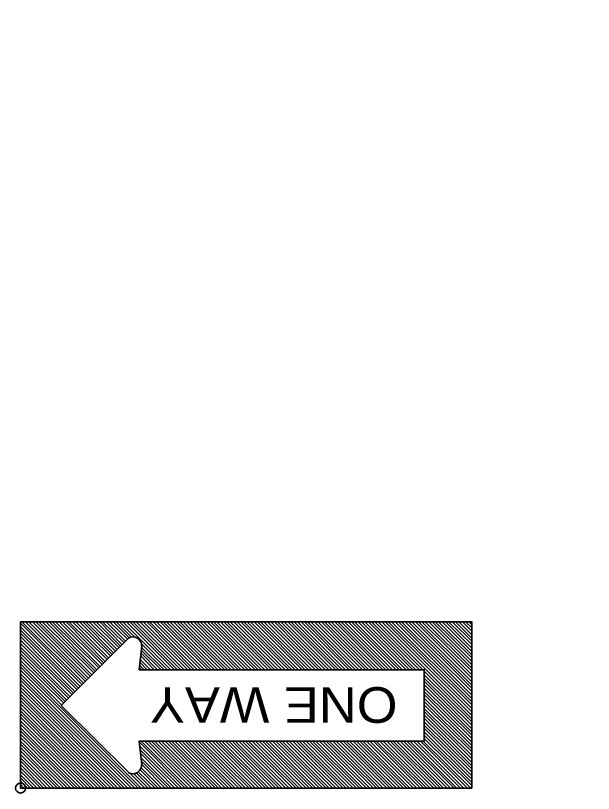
# Model space of a CAD drawing. Extents: x -133 to 547, y -328 to 112.
# Drawn here: x 275.99 to 299.34, y -0.08 to 31.36 of the extents above; entities that cross this region are included whole.
import ezdxf
from ezdxf.enums import TextEntityAlignment as Align

# ---------------------------------------------------------------- set-up
doc = ezdxf.new("R2010")
doc.units = 0
doc.header["$LTSCALE"] = 0.8
doc.header["$PDMODE"] = 32
doc.header["$PDSIZE"] = 0.4
doc.layers.add('1', color=7, linetype='Continuous', lineweight=35)

msp = doc.modelspace()

# ---------------------------------------------------------------- linework, layer by layer
at = {"layer": '1'}
for p, q in [((276.1893, 6.7957), (278.6692, 4.3157)), ((276.1893, 6.6557), (278.5892, 4.2557)), ((276.2493, 6.8557), (278.7292, 4.3757)), ((276.3893, 6.8557), (278.8092, 4.4557)), ((276.5292, 6.8557), (278.8692, 4.5157)), ((276.6692, 6.8557), (278.9292, 4.5957)), ((276.8092, 6.8557), (279.0093, 4.6557)), ((276.9292, 6.8557), (279.0693, 4.7157)), ((277.0693, 6.8557), (279.1492, 4.7957)), ((277.2092, 6.8557), (279.2092, 4.8557)), ((277.3492, 6.8557), (279.2692, 4.9157)), ((277.4692, 6.8557), (279.3492, 4.9957)), ((277.6092, 6.8557), (279.4092, 5.0557)), ((277.7493, 6.8557), (279.4892, 5.1357)), ((277.8893, 6.8557), (279.5492, 5.1957)), ((278.0292, 6.8557), (279.6092, 5.2557)), ((278.1492, 6.8557), (279.6893, 5.3357)), ((278.2892, 6.8557), (279.7493, 5.3957)), ((278.4292, 6.8557), (279.8293, 5.4757)), ((278.5693, 6.8557), (279.8893, 5.5357)), ((278.7092, 6.8557), (279.9493, 5.5957)), ((278.8293, 6.8557), (280.0292, 5.6757)), ((278.9692, 6.8557), (280.0892, 5.7357)), ((279.1092, 6.8557), (280.1692, 5.8157)), ((279.2493, 6.8557), (280.2292, 5.8757)), ((279.3893, 6.8557), (280.2892, 5.9357)), ((279.5093, 6.8557), (280.3692, 6.0157)), ((279.6492, 6.8557), (280.4292, 6.0757)), ((279.7892, 6.8557), (280.5093, 6.1557)), ((279.9292, 6.8557), (280.5693, 6.2157)), ((280.0492, 6.8557), (280.6692, 6.2357)), ((280.1893, 6.8557), (280.8092, 6.2357)), ((280.3293, 6.8557), (282.2692, 4.9157)), ((280.4692, 6.8557), (282.4092, 4.9157)), ((280.6092, 6.8557), (282.5292, 4.9157)), ((280.7292, 6.8557), (282.6692, 4.9157)), ((280.8692, 6.8557), (282.8092, 4.9157)), ((281.0093, 6.8557), (282.9493, 4.9157)), ((281.1492, 6.8557), (283.0892, 4.9157)), ((281.2892, 6.8557), (283.2092, 4.9157)), ((281.4092, 6.8557), (283.3492, 4.9157)), ((281.5492, 6.8557), (283.4892, 4.9157)), ((281.6893, 6.8557), (283.6293, 4.9157)), ((281.8293, 6.8557), (283.7692, 4.9157)), ((281.9493, 6.8557), (283.8893, 4.9157)), ((282.0892, 6.8557), (284.0292, 4.9157)), ((282.2292, 6.8557), (284.1692, 4.9157)), ((282.3692, 6.8557), (284.3092, 4.9157)), ((282.5093, 6.8557), (284.4493, 4.9157)), ((282.6293, 6.8557), (284.5693, 4.9157)), ((282.7692, 6.8557), (284.7092, 4.9157)), ((282.9092, 6.8557), (284.8492, 4.9157)), ((283.0492, 6.8557), (284.9892, 4.9157)), ((283.1893, 6.8557), (285.1092, 4.9157)), ((283.3092, 6.8557), (285.2493, 4.9157)), ((283.4493, 6.8557), (285.3893, 4.9157)), ((283.5892, 6.8557), (285.5292, 4.9157)), ((283.7292, 6.8557), (285.6692, 4.9157)), ((283.8692, 6.8557), (285.7892, 4.9157)), ((283.9892, 6.8557), (285.9292, 4.9157)), ((284.1293, 6.8557), (286.0693, 4.9157)), ((284.2692, 6.8557), (286.2092, 4.9157)), ((284.4092, 6.8557), (286.3492, 4.9157)), ((284.5292, 6.8557), (286.4692, 4.9157)), ((284.6692, 6.8557), (286.6092, 4.9157)), ((284.8092, 6.8557), (286.7493, 4.9157)), ((284.9493, 6.8557), (286.8893, 4.9157)), ((285.0892, 6.8557), (287.0292, 4.9157)), ((285.2092, 6.8557), (287.1492, 4.9157)), ((285.3492, 6.8557), (287.2892, 4.9157)), ((285.4892, 6.8557), (287.4292, 4.9157)), ((285.6293, 6.8557), (287.5693, 4.9157)), ((285.7692, 6.8557), (287.6893, 4.9157)), ((285.8893, 6.8557), (287.8293, 4.9157)), ((286.0292, 6.8557), (287.9692, 4.9157)), ((286.1692, 6.8557), (288.1092, 4.9157)), ((286.3092, 6.8557), (288.2493, 4.9157)), ((286.4493, 6.8557), (288.3692, 4.9157)), ((286.5693, 6.8557), (288.5093, 4.9157)), ((286.7092, 6.8557), (288.6492, 4.9157)), ((286.8492, 6.8557), (288.7892, 4.9157)), ((286.9892, 6.8557), (288.9292, 4.9157)), ((287.1092, 6.8557), (289.0492, 4.9157)), ((287.2493, 6.8557), (289.1893, 4.9157)), ((287.3893, 6.8557), (289.3293, 4.9157)), ((287.5292, 6.8557), (289.4692, 4.9157)), ((287.6692, 6.8557), (289.5892, 4.9157)), ((287.7892, 6.8557), (289.7292, 4.9157)), ((287.9292, 6.8557), (289.8692, 4.9157)), ((288.0693, 6.8557), (290.0093, 4.9157)), ((288.2092, 6.8557), (290.1492, 4.9157)), ((288.3492, 6.8557), (290.2692, 4.9157)), ((288.4692, 6.8557), (290.4092, 4.9157)), ((288.6092, 6.8557), (290.5492, 4.9157)), ((288.7493, 6.8557), (290.6893, 4.9157)), ((288.8893, 6.8557), (290.8293, 4.9157)), ((289.0093, 6.8557), (290.9493, 4.9157)), ((289.1492, 6.8557), (291.0892, 4.9157)), ((289.2892, 6.8557), (291.2292, 4.9157)), ((289.4292, 6.8557), (291.3692, 4.9157)), ((289.5693, 6.8557), (291.5093, 4.9157)), ((289.6893, 6.8557), (291.6293, 4.9157)), ((289.8293, 6.8557), (291.7692, 4.9157)), ((289.9692, 6.8557), (291.9092, 4.9157)), ((290.1092, 6.8557), (292.0492, 4.9157)), ((290.2493, 6.8557), (292.1692, 4.9157)), ((290.3692, 6.8557), (292.3092, 4.9157)), ((290.5093, 6.8557), (292.4493, 4.9157)), ((290.6492, 6.8557), (294.4292, 3.0757)), ((290.7892, 6.8557), (294.4292, 3.2157)), ((290.9292, 6.8557), (294.4292, 3.3557)), ((291.0492, 6.8557), (294.4292, 3.4957)), ((291.1893, 6.8557), (294.4292, 3.6157)), ((291.3293, 6.8557), (294.4292, 3.7557)), ((291.4692, 6.8557), (294.4292, 3.8957)), ((291.5892, 6.8557), (294.4292, 4.0357)), ((291.7292, 6.8557), (294.4292, 4.1757)), ((291.8692, 6.8557), (294.4292, 4.2957)), ((292.0093, 6.8557), (294.4292, 4.4357)), ((292.1492, 6.8557), (294.4292, 4.5757)), ((292.2692, 6.8557), (294.4292, 4.7157)), ((292.4092, 6.8557), (294.4292, 4.8557)), ((292.5492, 6.8557), (294.4292, 4.9757)), ((292.6893, 6.8557), (294.4292, 5.1157)), ((292.8293, 6.8557), (294.4292, 5.2557)), ((292.9493, 6.8557), (294.4292, 5.3957)), ((293.0892, 6.8557), (294.4292, 5.5157)), ((293.2292, 6.8557), (294.4292, 5.6557)), ((293.3692, 6.8557), (294.4292, 5.7957)), ((293.4892, 6.8557), (294.4292, 5.9357)), ((293.6293, 6.8557), (294.4292, 6.0757)), ((293.7692, 6.8557), (294.4292, 6.1957)), ((293.9092, 6.8557), (294.4292, 6.3357)), ((294.0492, 6.8557), (294.4292, 6.4757)), ((294.1692, 6.8557), (294.4292, 6.6157)), ((294.3092, 6.8557), (294.4292, 6.7557)), ((276.1893, 6.5157), (278.5292, 4.1757)), ((276.1893, 6.3957), (278.4692, 4.1157)), ((276.1893, 6.2557), (278.3893, 4.0357)), ((276.1893, 6.1157), (278.3293, 3.9757)), ((276.1893, 5.9757), (278.2692, 3.9157)), ((280.5492, 6.1957), (277.8293, 3.4757)), ((281.0693, 5.9757), (282.1293, 4.9157)), ((276.1893, 5.8357), (278.1893, 3.8357)), ((276.1893, 5.7157), (278.1293, 3.7757)), ((281.0693, 5.8357), (281.9892, 4.9157)), ((281.0693, 5.7157), (281.8692, 4.9157)), ((276.1893, 5.5757), (278.0492, 3.6957)), ((276.1893, 5.4357), (277.9892, 3.6357)), ((281.0492, 5.5957), (281.7292, 4.9157)), ((281.0492, 5.4757), (281.5892, 4.9157)), ((276.1893, 5.2957), (277.9292, 3.5757)), ((276.1893, 5.1557), (277.8492, 3.4957)), ((276.1893, 5.0357), (281.0693, 0.1357)), ((281.0093, 5.0957), (281.1893, 4.9157)), ((281.0292, 5.3357), (281.4493, 4.9157)), ((281.0292, 5.2157), (281.3092, 4.9157)), ((276.1893, 4.8957), (280.9493, 0.1357)), ((276.1893, 4.7557), (280.8092, 0.1357)), ((281.0093, 4.9757), (281.0492, 4.9157)), ((292.5093, 4.8557), (294.4292, 2.9357)), ((292.5093, 4.7157), (294.4292, 2.8157)), ((276.1893, 4.6157), (280.6692, 0.1357)), ((276.1893, 4.4957), (280.5292, 0.1357)), ((292.5093, 4.5757), (294.4292, 2.6757)), ((292.5093, 4.4557), (294.4292, 2.5357)), ((276.1893, 4.3557), (280.3893, 0.1357)), ((276.1893, 4.2157), (280.2692, 0.1357)), ((292.5093, 4.3157), (294.4292, 2.3957)), ((292.5093, 4.1757), (294.4292, 2.2757)), ((276.1893, 4.0757), (280.1293, 0.1357)), ((276.1893, 3.9357), (279.9892, 0.1357)), ((276.1893, 3.8157), (279.8492, 0.1357)), ((292.5093, 4.0357), (294.4292, 2.1357)), ((292.5093, 3.9157), (294.4292, 1.9957)), ((292.5093, 3.7757), (294.4292, 1.8557)), ((276.1893, 3.6757), (279.7092, 0.1357)), ((276.1893, 3.5357), (279.5892, 0.1357)), ((277.8293, 3.4757), (280.5492, 0.7757)), ((292.5093, 3.6357), (294.4292, 1.7157)), ((292.5093, 3.4957), (294.4292, 1.5957)), ((276.1893, 3.3957), (279.4493, 0.1357)), ((276.1893, 3.2557), (279.3092, 0.1357)), ((292.5093, 3.3557), (294.4292, 1.4557)), ((292.5093, 3.2357), (294.4292, 1.3157)), ((276.1893, 3.1357), (279.1692, 0.1357)), ((276.1893, 2.9957), (279.0492, 0.1357)), ((276.1893, 2.8557), (278.9092, 0.1357)), ((292.5093, 3.0957), (294.4292, 1.1757)), ((292.5093, 2.9557), (294.4292, 1.0357)), ((276.1893, 2.7157), (278.7692, 0.1357)), ((276.1893, 2.5757), (278.6293, 0.1357)), ((292.5093, 2.8157), (294.4292, 0.9157)), ((292.5093, 2.6757), (294.4292, 0.7757)), ((292.5093, 2.5557), (294.4292, 0.6357)), ((276.1893, 2.4557), (278.4892, 0.1357)), ((276.1893, 2.3157), (278.3692, 0.1357)), ((292.5093, 2.4157), (294.4292, 0.4957)), ((292.5093, 2.2757), (294.4292, 0.3557)), ((276.1893, 2.1757), (278.2292, 0.1357)), ((276.1893, 2.0357), (278.0892, 0.1357)), ((276.1893, 1.9157), (277.9493, 0.1357)), ((281.0093, 1.9757), (282.8492, 0.1357)), ((281.0693, 2.0357), (282.9692, 0.1357)), ((281.2092, 2.0357), (283.1092, 0.1357)), ((281.3492, 2.0357), (283.2493, 0.1357)), ((281.4892, 2.0357), (283.3893, 0.1357)), ((281.6092, 2.0357), (283.5292, 0.1357)), ((281.7493, 2.0357), (283.6492, 0.1357)), ((281.8893, 2.0357), (283.7892, 0.1357)), ((282.0292, 2.0357), (283.9292, 0.1357)), ((282.1692, 2.0357), (284.0693, 0.1357)), ((282.2892, 2.0357), (284.1893, 0.1357)), ((282.4292, 2.0357), (284.3293, 0.1357)), ((282.5693, 2.0357), (284.4692, 0.1357)), ((282.7092, 2.0357), (284.6092, 0.1357)), ((282.8492, 2.0357), (284.7493, 0.1357)), ((282.9692, 2.0357), (284.8692, 0.1357)), ((283.1092, 2.0357), (285.0093, 0.1357)), ((283.2493, 2.0357), (285.1492, 0.1357)), ((283.3893, 2.0357), (285.2892, 0.1357)), ((283.5093, 2.0357), (285.4292, 0.1357)), ((283.6492, 2.0357), (285.5492, 0.1357)), ((283.7892, 2.0357), (285.6893, 0.1357)), ((283.9292, 2.0357), (285.8293, 0.1357)), ((284.0693, 2.0357), (285.9692, 0.1357)), ((284.1893, 2.0357), (286.1092, 0.1357)), ((284.3293, 2.0357), (286.2292, 0.1357)), ((284.4692, 2.0357), (286.3692, 0.1357)), ((284.6092, 2.0357), (286.5093, 0.1357)), ((284.7493, 2.0357), (286.6492, 0.1357)), ((284.8692, 2.0357), (286.7692, 0.1357)), ((285.0093, 2.0357), (286.9092, 0.1357)), ((285.1492, 2.0357), (287.0492, 0.1357)), ((285.2892, 2.0357), (287.1893, 0.1357)), ((285.4092, 2.0357), (287.3293, 0.1357)), ((285.5492, 2.0357), (287.4493, 0.1357)), ((285.6893, 2.0357), (287.5892, 0.1357)), ((285.8293, 2.0357), (287.7292, 0.1357)), ((285.9692, 2.0357), (287.8692, 0.1357)), ((286.0892, 2.0357), (288.0093, 0.1357)), ((286.2292, 2.0357), (288.1293, 0.1357)), ((286.3692, 2.0357), (288.2692, 0.1357)), ((286.5093, 2.0357), (288.4092, 0.1357)), ((286.6492, 2.0357), (288.5492, 0.1357)), ((286.7692, 2.0357), (288.6692, 0.1357)), ((286.9092, 2.0357), (288.8092, 0.1357)), ((287.0492, 2.0357), (288.9493, 0.1357)), ((287.1893, 2.0357), (289.0892, 0.1357)), ((287.3293, 2.0357), (289.2292, 0.1357)), ((287.4493, 2.0357), (289.3492, 0.1357)), ((287.5892, 2.0357), (289.4892, 0.1357)), ((287.7292, 2.0357), (289.6293, 0.1357)), ((287.8692, 2.0357), (289.7692, 0.1357)), ((287.9892, 2.0357), (289.9092, 0.1357)), ((288.1293, 2.0357), (290.0292, 0.1357)), ((288.2692, 2.0357), (290.1692, 0.1357)), ((288.4092, 2.0357), (290.3092, 0.1357)), ((288.5492, 2.0357), (290.4493, 0.1357)), ((288.6692, 2.0357), (290.5892, 0.1357)), ((288.8092, 2.0357), (290.7092, 0.1357)), ((288.9493, 2.0357), (290.8492, 0.1357)), ((289.0892, 2.0357), (290.9892, 0.1357)), ((289.2292, 2.0357), (291.1293, 0.1357)), ((289.3492, 2.0357), (291.2493, 0.1357)), ((289.4892, 2.0357), (291.3893, 0.1357)), ((289.6293, 2.0357), (291.5292, 0.1357)), ((289.7692, 2.0357), (291.6692, 0.1357)), ((289.9092, 2.0357), (291.8092, 0.1357)), ((290.0292, 2.0357), (291.9292, 0.1357)), ((290.1692, 2.0357), (292.0693, 0.1357)), ((290.3092, 2.0357), (292.2092, 0.1357)), ((290.4493, 2.0357), (292.3492, 0.1357)), ((290.5693, 2.0357), (292.4892, 0.1357)), ((290.7092, 2.0357), (292.6092, 0.1357)), ((290.8492, 2.0357), (292.7493, 0.1357)), ((290.9892, 2.0357), (292.8893, 0.1357)), ((291.1293, 2.0357), (293.0292, 0.1357)), ((291.2493, 2.0357), (293.1692, 0.1357)), ((291.3893, 2.0357), (293.2892, 0.1357)), ((291.5292, 2.0357), (293.4292, 0.1357)), ((291.6692, 2.0357), (293.5693, 0.1357)), ((291.8092, 2.0357), (293.7092, 0.1357)), ((291.9292, 2.0357), (293.8293, 0.1357)), ((292.0693, 2.0357), (293.9692, 0.1357)), ((292.2092, 2.0357), (294.1092, 0.1357)), ((292.3492, 2.0357), (294.2493, 0.1357)), ((292.4692, 2.0357), (294.3893, 0.1357)), ((292.5093, 2.1357), (294.4292, 0.2357)), ((276.1893, 1.7757), (277.8092, 0.1357)), ((276.1893, 1.6357), (277.6893, 0.1357)), ((281.0093, 1.8357), (282.7092, 0.1357)), ((281.0292, 1.6757), (282.5693, 0.1357)), ((276.1893, 1.4957), (277.5492, 0.1357)), ((276.1893, 1.3557), (277.4092, 0.1357)), ((281.0492, 1.5357), (282.4292, 0.1357)), ((281.0492, 1.3757), (282.2892, 0.1357)), ((276.1893, 1.2357), (277.2692, 0.1357)), ((276.1893, 1.0957), (277.1293, 0.1357)), ((276.1893, 0.9557), (277.0093, 0.1357)), ((281.0693, 1.2357), (282.1692, 0.1357)), ((281.0693, 0.9557), (281.8893, 0.1357)), ((281.0892, 1.0957), (282.0292, 0.1357)), ((276.1893, 0.8157), (276.8692, 0.1357)), ((276.1893, 0.6757), (276.7292, 0.1357)), ((280.6092, 0.7357), (281.2092, 0.1357)), ((280.7692, 0.7157), (281.3492, 0.1357)), ((280.8692, 0.7557), (281.4892, 0.1357)), ((280.9493, 0.7957), (281.6293, 0.1357)), ((281.0292, 0.8757), (281.7493, 0.1357)), ((276.1893, 0.5557), (276.5892, 0.1357)), ((276.1893, 0.4157), (276.4692, 0.1357)), ((276.1893, 0.2757), (276.3293, 0.1357))]:
    msp.add_line(p, q, dxfattribs=at)
msp.add_lwpolyline([(276.1893, 0.1357), (294.4292, 0.1357), (294.4292, 6.8557), (276.1893, 6.8557)], close=True, dxfattribs=at)
msp.add_lwpolyline([(281.0892, 1.0957), (280.9892, 2.0357), (292.5093, 2.0357), (292.5093, 4.9157), (280.9892, 4.9157), (281.0892, 5.8757)], dxfattribs=at)
at = {"layer": '1', "lineweight": 53}
msp.add_arc((297.706, 31.355), 50, 270, 0, dxfattribs=at)
at = {"layer": '1'}
for centre, start, end in [((280.7316, 5.8996), 356.63551, 121.23355), ((280.7316, 1.066), 238.76645, 3.36449)]:
    msp.add_arc(centre, 0.3492, start, end, dxfattribs=at)
msp.add_point((276.1893, 0.1357), dxfattribs=at)

# ---------------------------------------------------------------- texts
at = {"layer": '1', "width": 1.1}
msp.add_text('ONE WAY', height=1.44, rotation=180, dxfattribs=at).set_placement((286.4236, 4.2139), align=Align.CENTER)

doc.saveas('drawing.dxf')
